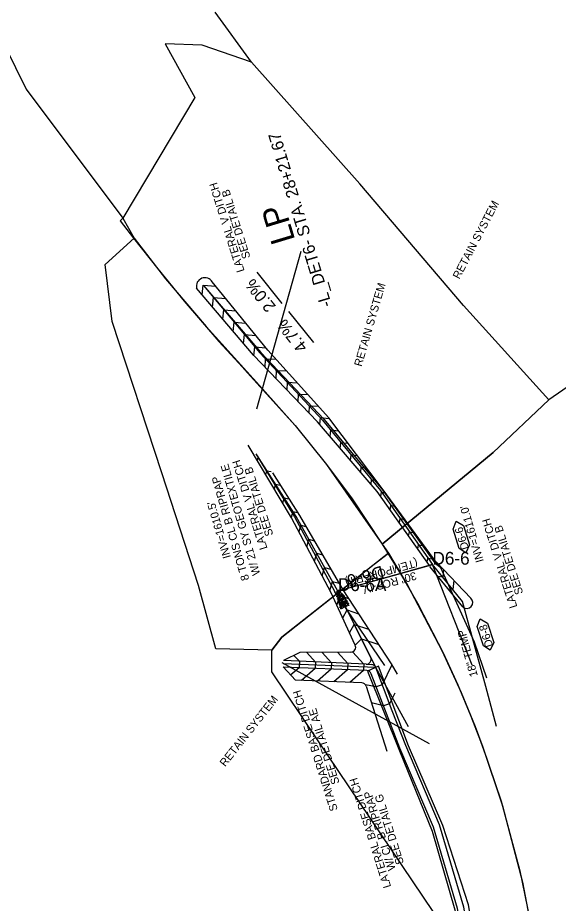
# Model space of a CAD drawing. Extents: x 465700 to 483515, y 488970 to 507540.
# Drawn here: x 474334 to 474671, y 504814 to 505367 of the extents above; entities that cross this region are included whole.
import ezdxf

# ---------------------------------------------------------------- set-up
doc = ezdxf.new("R2010")
doc.units = 0
for name, color, linetype in [('Exist Plan Preparation Watershed Blue', 7, 'Continuous'), ('Prop Drainage Structure Box Number Symbol CELL', 7, 'Continuous'), ('Prop Drainage Structure Pipe Collar Label', 7, 'Continuous'), ('Prop Drainage Structure Pipe RCP 30in Class IV', 7, 'Continuous'), ('Prop Drainage Structure Pipe RCP 30in Class IV Label', 7, 'Continuous'), ('Prop Drainage Structure Pipe Side Drain 18in', 7, 'Continuous'), ('Prop Drainage Structure Pipe Side Drain 18in Label', 7, 'Continuous'), ('Prop Drainage Structure Pipe Stub Out CELL', 7, 'Continuous'), ('Prop Drainage Structure Tops and Inverts LABEL', 7, 'Continuous'), ('Prop Earthen Structure Ditch Flow Line', 7, 'Continuous'), ('Prop Earthen Structure Head Ditch', 7, 'Continuous'), ('Prop Erosion Rip Rap Class B', 7, 'Continuous'), ('Prop Erosion Rip Rap Pad at Outlet CELL', 7, 'Continuous'), ('Prop Erosion Rip Rap Pad at Outlet Label', 7, 'Continuous'), ('Prop Plan Preparation Sag', 7, 'Continuous'), ('Prop Plan Preparation Sag Label', 7, 'Continuous'), ('Scratch_Level_4', 7, 'Continuous'), ('Scratch_Level_8', 7, 'Continuous')]:
    doc.layers.add(name, color=color, linetype=linetype)

msp = doc.modelspace()

# ---------------------------------------------------------------- linework, layer by layer
at = {"layer": 'Exist Plan Preparation Watershed Blue'}
for points in [[(474286.06, 505429.98), (474339.1, 505322.33), (474399.33, 505241.75), (474406.41, 505229.29), (474426.11, 505203.87), (474451.48, 505174.21), (474486.5, 505135.22), (474506.91, 505112.32), (474526.54, 505087.97), (474561.34, 505038.16), (474577.08, 505012.49), (474598.56, 504971.69), (474608.48, 504950.2), (474619.28, 504924.18), (474624.17, 504911.28), (474636.37, 504874.75), (474648.84, 504827.06), (474655.42, 504793.19)], [(474927.77, 504713.75), (474882, 504859.82), (474796.36, 504994.66), (474755.09, 505146.54), (474710.28, 505159.29), (474665.31, 505128.41), (474612.14, 505187.24), (474547.27, 505263.26), (474479.75, 505339.2), (474457.09, 505370.44)]]:
    msp.add_lwpolyline(points, dxfattribs=at)
at = {"layer": 'Prop Drainage Structure Box Number Symbol CELL'}
for points in [[(474609.38, 505035.52), (474605.61, 505047.55), (474607.47, 505052.43), (474612.06, 505049.74), (474615.83, 505037.71), (474613.61, 505032.82), (474609.38, 505035.52)], [(474624.47, 504974.65), (474620.71, 504986.68), (474622.57, 504991.56), (474627.16, 504988.87), (474630.93, 504976.84), (474628.71, 504971.95), (474624.47, 504974.65)]]:
    msp.add_lwpolyline(points, dxfattribs=at)
at = {"layer": 'Prop Drainage Structure Pipe RCP 30in Class IV'}
msp.add_line((474592.73, 505025.37), (474533.61, 505008.87), dxfattribs=at)
at = {"layer": 'Prop Drainage Structure Pipe Side Drain 18in'}
msp.add_line((474625.96, 504949.34), (474611.38, 505002.44), dxfattribs=at)
at = {"layer": 'Prop Drainage Structure Pipe Stub Out CELL'}
msp.add_line((474592.72, 505025.35), (474592.72, 505025.35), dxfattribs=at)
msp.add_line((474592.72, 505025.35), (474592.72, 505025.35), dxfattribs=at)
msp.add_lwpolyline([(474592.72, 505025.36), (474592.74, 505025.35), (474592.73, 505025.33), (474592.71, 505025.34), (474592.72, 505025.36)], dxfattribs=at)
at = {"layer": 'Prop Earthen Structure Ditch Flow Line'}
for p, q in [((474632.62, 504924.28), (474625.96, 504949.34)), ((474576, 504912.31), (474567.64, 504934.12)), ((474572.32, 504910.74), (474566.52, 504925.87))]:
    msp.add_line(p, q, dxfattribs=at)
for points in [[(474622.86, 504705.91), (474617.92, 504758.57), (474608.42, 504810.58), (474593.3, 504861.45), (474572.32, 504910.74)], [(474626.84, 504706.28), (474621.89, 504759.11), (474612.32, 504811.51), (474597.07, 504862.8), (474576, 504912.31)]]:
    msp.add_lwpolyline(points, dxfattribs=at)
at = {"layer": 'Prop Earthen Structure Head Ditch'}
for p, q in [((474611.38, 505002.44), (474592.73, 505025.37)), ((474617.47, 504962.68), (474592.73, 505025.37)), ((474563.04, 504962.47), (474531.69, 505008.33)), ((474590.77, 504913.46), (474498.94, 504963.98)), ((474551.83, 504959.16), (474499.43, 504961.43)), ((474557.29, 504961.03), (474499.52, 504963.42)), ((474551.27, 504963.18), (474499.61, 504965.42)), ((474551.27, 504963.18), (474499.61, 504965.42)), ((474551.27, 504963.18), (474554.62, 504963.04)), ((474567.64, 504934.12), (474557.29, 504961.12)), ((474577.8, 504924.06), (474557.29, 504961.03)), ((474566.96, 504963.46), (474570.74, 504956.86)), ((474566.52, 504925.87), (474554.5, 504957.23)), ((474551.35, 504949.45), (474564.21, 504908.92))]:
    msp.add_line(p, q, dxfattribs=at)
for points in [[(474448.94, 505193.9), (474449.48, 505199.97), (474457.44, 505199.27)], [(474449.69, 505199.72), (474485.49, 505157.78), (474525.05, 505116.04), (474561.61, 505072.06), (474594.66, 505025.9)], [(474449.69, 505199.72), (474485.02, 505157.61), (474524.1, 505115.72), (474560.18, 505071.62), (474592.73, 505025.37)], [(474449.69, 505199.72), (474485.02, 505157.61), (474524.1, 505115.72), (474560.18, 505071.62), (474592.73, 505025.37)], [(474595.59, 505026.16), (474561.96, 505072.17), (474527.96, 505117.02), (474489.96, 505159.41), (474455.27, 505201.93)], [(474590.81, 505024.83), (474558.26, 505071.03), (474520.84, 505114.63), (474481.02, 505156.14), (474445.43, 505198.03)], [(474455.41, 505186.28), (474455.94, 505192.27), (474463.71, 505191.59)], [(474461.88, 505178.67), (474462.4, 505184.57), (474469.97, 505183.91)], [(474468.35, 505171.06), (474468.86, 505176.87), (474476.24, 505176.23)], [(474474.82, 505163.44), (474475.32, 505169.17), (474482.51, 505168.55)], [(474481.28, 505155.83), (474481.78, 505161.48), (474488.77, 505160.86)], [(474488.25, 505148.6), (474488.43, 505153.95), (474495.06, 505153.72)], [(474495.11, 505141.45), (474495.29, 505146.6), (474501.64, 505146.38)], [(474501.97, 505134.29), (474502.15, 505139.25), (474508.22, 505139.04)], [(474508.84, 505127.14), (474509, 505131.91), (474514.8, 505131.7)], [(474515.7, 505119.99), (474515.86, 505124.56), (474521.38, 505124.37)], [(474522.37, 505112.85), (474522.81, 505117.3), (474528.16, 505116.76)], [(474528.76, 505105.39), (474529.18, 505109.52), (474534.02, 505109.03)], [(474544.53, 504975.02), (474529.45, 505007.71), (474504.73, 505054.57), (474477.64, 505100.1)], [(474535.16, 505097.94), (474535.54, 505101.74), (474539.88, 505101.3)], [(474482.42, 505094.57), (474506.59, 505055.15), (474531.69, 505008.33)], [(474554.09, 504967.51), (474533.61, 505008.87), (474507.57, 505055.45), (474483, 505093.9)], [(474557.29, 504961.03), (474533.61, 505008.87), (474507.57, 505055.45), (474483, 505093.9)], [(474541.56, 505090.49), (474541.9, 505093.96), (474545.73, 505093.58)], [(474483.41, 505090.4), (474483.87, 505092.53), (474484.26, 505092.45)], [(474488.72, 505081.48), (474489.29, 505084.06), (474492.04, 505083.46)], [(474492.74, 505082.64), (474509.68, 505056.1), (474536.7, 505009.73), (474566.96, 504963.46)], [(474547.95, 505083.04), (474548.27, 505086.18), (474551.59, 505085.85)], [(474554.35, 505075.58), (474554.63, 505078.4), (474557.45, 505078.12)], [(474494.03, 505072.55), (474494.7, 505075.59), (474497.66, 505074.94)], [(474499.34, 505063.63), (474500.11, 505067.12), (474503.06, 505066.47)], [(474560.46, 505067.91), (474560.92, 505070.57), (474563.45, 505070.13)], [(474566.24, 505059.69), (474566.7, 505062.35), (474569.49, 505061.87)], [(474504.65, 505054.7), (474505.52, 505058.66), (474508.46, 505058.01)], [(474509.4, 505045.71), (474510.62, 505050), (474513.75, 505049.11)], [(474572.03, 505051.48), (474572.49, 505054.13), (474575.53, 505053.6)], [(474577.81, 505043.27), (474578.27, 505045.91), (474581.57, 505045.34)], [(474514.21, 505036.59), (474515.52, 505041.23), (474518.9, 505040.27)], [(474519.02, 505027.48), (474520.42, 505032.45), (474524.06, 505031.43)], [(474583.6, 505035.06), (474584.06, 505037.69), (474587.61, 505037.08)], [(474589.38, 505026.85), (474589.84, 505029.47), (474593.65, 505028.81)], [(474616.67, 505004.4), (474595.21, 505026.99)], [(474523.83, 505018.36), (474525.33, 505023.68), (474529.21, 505022.59)], [(474611.74, 504998.92), (474591.06, 505024.27)], [(474626.66, 504954.4), (474619.05, 504976.87), (474597.95, 505023.39), (474594.66, 505025.9)], [(474599.58, 505022.37), (474599.1, 505017.59), (474596.29, 505017.87)], [(474528.63, 505009.25), (474530.23, 505014.91), (474534.36, 505013.74)], [(474606.03, 505015.53), (474605.46, 505009.81), (474602.64, 505010.09)], [(474532.97, 505000.06), (474535, 505006.07), (474540.26, 505004.29)], [(474536.65, 504992.09), (474539.46, 504997.06), (474546.55, 504994.66)], [(474540.95, 504982.78), (474543.92, 504988.05), (474552.85, 504985.04)], [(474544.53, 504975.02), (474548.38, 504979.05), (474559.14, 504975.41)], [(474541.83, 504970.76), (474509.95, 504970.48), (474499.61, 504965.42)], [(474506.26, 504968.68), (474509.65, 504964.99), (474509.47, 504960.97), (474504.29, 504956.46)], [(474514.22, 504970.52), (474519.69, 504964.55), (474519.51, 504960.53), (474510.98, 504953.1)], [(474523.78, 504970.6), (474529.73, 504964.12), (474529.56, 504960.1), (474521.04, 504952.69)], [(474533.35, 504970.69), (474539.77, 504963.68), (474539.6, 504959.66), (474531.1, 504952.27)], [(474542.77, 504970.92), (474549.81, 504963.25), (474549.64, 504959.23), (474541.16, 504951.85)], [(474548.62, 504951.54), (474507.24, 504953.26), (474499.53, 504961.64)], [(474567.39, 504962.71), (474561.41, 504950.36), (474557.6, 504949.03), (474550.87, 504950.38)], [(474569.14, 504945.1), (474565.92, 504938.46), (474562.12, 504937.14), (474554.68, 504938.96)]]:
    msp.add_lwpolyline(points, dxfattribs=at)
for centre, radius, start, end in [((474450.65, 505199.24), 5.35, 30.2073, 192.9709), ((474614.21, 505001.66), 3.69, 227.9713, 47.9713), ((474541.8, 504973.76), 3, 270.5081, 24.769), ((474551.4, 504966.18), 3, 267.5195, 26.338), ((474554.49, 504960.04), 3, 20.9736, 87.5195), ((474551.7, 504956.16), 3, 20.9736, 87.5195), ((474548.49, 504948.55), 3, 17.5981, 87.629)]:
    msp.add_arc(centre, radius, start, end, dxfattribs=at)
at = {"layer": 'Prop Erosion Rip Rap Class B'}
for p, q in [((474559.04, 504962), (474552.1, 504958.94)), ((474577.66, 504912.17), (474559.04, 504962)), ((474552.1, 504958.94), (474572.16, 504909.07))]:
    msp.add_line(p, q, dxfattribs=at)
msp.add_lwpolyline([(474572.16, 504909.07), (474592.55, 504859), (474606.77, 504809.82), (474615.79, 504757.68), (474620.45, 504704.65), (474625.47, 504653.43), (474631.73, 504706.41), (474624.46, 504759.64), (474615.2, 504812.86), (474599.15, 504862.42), (474577.66, 504912.17)], dxfattribs=at)
at = {"layer": 'Prop Erosion Rip Rap Pad at Outlet CELL'}
msp.add_line((474533.63, 505008.86), (474533.63, 505008.86), dxfattribs=at)
msp.add_line((474533.63, 505008.86), (474533.63, 505008.86), dxfattribs=at)
for points in [[(474532.62, 505007.2), (474532.9, 505007.54), (474533.64, 505008.26), (474534.33, 505008.06), (474534.53, 505007.56), (474533.59, 505006.77), (474532.95, 505006.78), (474532.67, 505007.09)], [(474533.76, 505008.59), (474533.6, 505008.43), (474533.26, 505008.01), (474532.95, 505008.18), (474532.87, 505008.35), (474533.29, 505008.87), (474533.63, 505008.86), (474533.76, 505008.59)], [(474533.63, 505005.56), (474533.35, 505005.62), (474533.02, 505006.01), (474533.13, 505006.31), (474533.3, 505006.39), (474533.76, 505005.96), (474533.76, 505005.71), (474533.63, 505005.56)], [(474533.62, 505004.84), (474533.35, 505004.96), (474533.02, 505005.34), (474533.1, 505005.63), (474533.3, 505005.73), (474533.75, 505005.25), (474533.74, 505005.02), (474533.62, 505004.84)], [(474533.32, 505006.54), (474533.52, 505006.65), (474533.92, 505006.86), (474534.16, 505006.64), (474534.24, 505006.47), (474533.71, 505006.2), (474533.35, 505006.26), (474533.32, 505006.54)], [(474534.6, 505009.16), (474534.44, 505008.99), (474534.07, 505008.55), (474533.8, 505008.75), (474533.71, 505008.92), (474534.11, 505009.39), (474534.46, 505009.43), (474534.6, 505009.16)], [(474536.19, 505003.71), (474535.34, 505003.83), (474533.79, 505004.63), (474533.77, 505005.84), (474534.37, 505006.41), (474536.32, 505005.47), (474536.65, 505004.54), (474536.34, 505003.65)], [(474534.12, 505006.95), (474534.51, 505007.28), (474535.41, 505007.74), (474536.03, 505007.28), (474536.04, 505006.83), (474534.9, 505006.34), (474534.35, 505006.54), (474534.12, 505006.95)], [(474535.02, 505007.57), (474534.72, 505007.76), (474534.25, 505008.19), (474534.37, 505008.72), (474534.73, 505008.9), (474535.31, 505008.19), (474535.27, 505007.83), (474535.02, 505007.57)], [(474535.72, 505005.76), (474535.44, 505005.82), (474535.13, 505006.21), (474535.21, 505006.52), (474535.39, 505006.56), (474535.83, 505006.15), (474535.84, 505005.95), (474535.72, 505005.76)], [(474536.31, 505005.77), (474536.01, 505005.88), (474535.74, 505006.27), (474535.79, 505006.56), (474536, 505006.66), (474536.45, 505006.17), (474536.43, 505005.95), (474536.31, 505005.77)], [(474536.77, 505006.14), (474536.48, 505006.2), (474536.17, 505006.59), (474536.26, 505006.89), (474536.44, 505006.94), (474536.87, 505006.52), (474536.89, 505006.32), (474536.77, 505006.14)], [(474536.35, 505005.76), (474536.65, 505006.04), (474537.19, 505006.31), (474537.62, 505005.95), (474537.62, 505005.61), (474536.81, 505005.3), (474536.47, 505005.5), (474536.35, 505005.76)], [(474537.32, 505003.99), (474537.06, 505004.07), (474536.77, 505004.46), (474536.84, 505004.76), (474537.04, 505004.86), (474537.46, 505004.39), (474537.44, 505004.17), (474537.32, 505003.99)], [(474537.87, 505004.59), (474537.59, 505004.66), (474537.28, 505005.05), (474537.36, 505005.34), (474537.55, 505005.39), (474537.98, 505004.99), (474537.99, 505004.78), (474537.87, 505004.59)], [(474538.46, 505004.56), (474538.37, 505004.31), (474538.05, 505004.02), (474537.7, 505004.06), (474537.55, 505004.35), (474538.05, 505004.69), (474538.36, 505004.73), (474538.46, 505004.56)], [(474533.36, 505004.02), (474533.6, 505004.23), (474534.02, 505004.49), (474534.26, 505004.23), (474534.32, 505003.97), (474533.72, 505003.75), (474533.42, 505003.85), (474533.36, 505004.02)], [(474534.39, 505002.16), (474534.12, 505002.22), (474533.79, 505002.61), (474533.9, 505002.91), (474534.07, 505002.99), (474534.54, 505002.56), (474534.53, 505002.31), (474534.39, 505002.16)], [(474533.85, 505003.3), (474534.01, 505003.63), (474534.53, 505004.11), (474534.96, 505003.99), (474535.09, 505003.72), (474534.5, 505003.07), (474534.07, 505003.07), (474533.85, 505003.3)], [(474534.67, 505001.16), (474534.39, 505001.22), (474534.07, 505001.6), (474534.17, 505001.9), (474534.34, 505001.98), (474534.81, 505001.56), (474534.81, 505001.31), (474534.67, 505001.16)], [(474535.25, 505003.03), (474535.11, 505002.84), (474534.76, 505002.44), (474534.44, 505002.64), (474534.37, 505002.79), (474534.81, 505003.26), (474535.02, 505003.25), (474535.25, 505003.03)], [(474534.55, 505002.21), (474534.98, 505002.54), (474535.92, 505002.91), (474536.46, 505002.5), (474536.54, 505001.96), (474535.43, 505001.51), (474534.73, 505001.71), (474534.55, 505002.21)], [(474535.26, 504999.92), (474534.97, 505000.07), (474534.62, 505000.44), (474534.74, 505000.71), (474534.9, 505000.78), (474535.39, 505000.35), (474535.38, 505000.1), (474535.26, 504999.92)], [(474535.6, 505001.27), (474535.44, 505001.11), (474535.05, 505000.8), (474534.75, 505000.89), (474534.68, 505001.02), (474535.01, 505001.45), (474535.33, 505001.48), (474535.52, 505001.35)], [(474534.81, 504998.83), (474535.05, 504999.04), (474535.46, 504999.29), (474535.71, 504999.04), (474535.77, 504998.77), (474535.17, 504998.55), (474534.87, 504998.65), (474534.81, 504998.83)], [(474534.83, 504999.52), (474535.06, 504999.74), (474535.48, 504999.99), (474535.72, 504999.74), (474535.78, 504999.47), (474535.18, 504999.25), (474534.88, 504999.35), (474534.83, 504999.52)], [(474535.69, 505002.96), (474535.42, 505003.01), (474535.12, 505003.42), (474535.18, 505003.7), (474535.38, 505003.8), (474535.83, 505003.36), (474535.83, 505003.11), (474535.69, 505002.96)], [(474535.92, 505000.2), (474535.77, 505000.34), (474535.37, 505000.69), (474535.53, 505001.03), (474535.7, 505001.11), (474536.19, 505000.64), (474536.07, 505000.4), (474535.92, 505000.2)], [(474535.67, 504998.95), (474536.1, 504999.25), (474536.95, 504999.71), (474537.58, 504999.24), (474537.6, 504998.71), (474536.5, 504998.24), (474535.91, 504998.48), (474535.67, 504998.95)], [(474536.41, 505000.8), (474536.1, 505000.89), (474535.79, 505001.28), (474535.89, 505001.58), (474536.07, 505001.64), (474536.5, 505001.22), (474536.53, 505000.98), (474536.41, 505000.8)], [(474537.21, 505000.22), (474536.98, 504999.91), (474536.4, 504999.48), (474536, 504999.62), (474535.87, 504999.89), (474536.5, 505000.45), (474536.88, 505000.53), (474537.21, 505000.22)], [(474536, 505003.47), (474536.22, 505003.71), (474536.63, 505003.8), (474536.96, 505003.58), (474536.94, 505003.37), (474536.4, 505003.1), (474536.08, 505003.3), (474536, 505003.47)], [(474538.55, 505003.43), (474538.26, 505002.99), (474537.48, 505002.09), (474536.59, 505002.44), (474536.37, 505002.87), (474537.45, 505003.89), (474538.21, 505003.95), (474538.66, 505003.5)], [(474537, 505002.13), (474537.34, 505001.85), (474538.07, 505001.08), (474537.85, 505000.44), (474537.39, 505000.2), (474536.61, 505001.15), (474536.47, 505001.76), (474536.91, 505002.05)], [(474538.2, 505001.42), (474537.96, 505001.49), (474537.57, 505001.9), (474537.68, 505002.2), (474537.86, 505002.24), (474538.33, 505001.82), (474538.36, 505001.62), (474538.2, 505001.42)], [(474537.6, 504999.47), (474537.89, 504999.69), (474538.46, 504999.98), (474538.88, 504999.6), (474538.94, 504999.31), (474538.05, 504998.98), (474537.71, 504999.15), (474537.6, 504999.47)], [(474538.39, 504999.87), (474538.1, 504999.95), (474537.77, 505000.33), (474537.87, 505000.63), (474538.04, 505000.71), (474538.52, 505000.27), (474538.52, 505000.02), (474538.39, 504999.87)], [(474538, 505002.34), (474538.22, 505002.58), (474538.63, 505002.67), (474538.96, 505002.45), (474538.94, 505002.23), (474538.4, 505001.96), (474538.08, 505002.17), (474538, 505002.34)], [(474538.79, 505001.33), (474539.24, 505001.1), (474539.96, 505000.36), (474539.76, 504999.67), (474539.24, 504999.55), (474538.42, 505000.47), (474538.39, 505000.96), (474538.75, 505001.39)], [(474539.15, 505002.54), (474538.86, 505002.6), (474538.55, 505002.99), (474538.62, 505003.29), (474538.81, 505003.33), (474539.24, 505002.93), (474539.26, 505002.73), (474539.15, 505002.54)], [(474539.69, 505002.12), (474539.55, 505001.81), (474539.2, 505001.54), (474538.87, 505001.58), (474538.73, 505001.84), (474539.24, 505002.18), (474539.53, 505002.25), (474539.69, 505002.12)], [(474539.3, 505001.12), (474539.52, 505001.35), (474539.94, 505001.44), (474540.25, 505001.21), (474540.23, 505001), (474539.7, 505000.72), (474539.38, 505000.95), (474539.3, 505001.12)], [(474540.49, 504999.76), (474540.2, 504999.82), (474539.89, 505000.21), (474539.98, 505000.51), (474540.17, 505000.56), (474540.59, 505000.16), (474540.61, 504999.95), (474540.49, 504999.76)], [(474535.39, 504998), (474535.62, 504998.21), (474536.04, 504998.46), (474536.29, 504998.21), (474536.35, 504997.94), (474535.75, 504997.72), (474535.45, 504997.82), (474535.39, 504998)]]:
    msp.add_lwpolyline(points, dxfattribs=at)
at = {"layer": 'Prop Plan Preparation Sag'}
msp.add_line((474483.14, 505122.61), (474510.69, 505221.09), dxfattribs=at)
at = {"layer": 'Prop Plan Preparation Sag Label'}
for p, q in [((474498.83, 505188.5), (474483.21, 505208.02)), ((474502.78, 505183.56), (474518.4, 505164.05))]:
    msp.add_line(p, q, dxfattribs=at)
at = {"layer": 'Scratch_Level_4'}
for points in [[(474425.87, 505350.71), (474444.35, 505317.14), (474399.33, 505241.75), (474397.78, 505240.2), (474406.09, 505229.32), (474421.19, 505210.16), (474437.68, 505189.99), (474459.36, 505164.8), (474486.5, 505135.22), (474506.91, 505112.32), (474526.54, 505087.97), (474542.57, 505066.45), (474561.34, 505038.16), (474630.64, 505095.35), (474665.31, 505128.41), (474612.14, 505187.24), (474547.27, 505263.26), (474479.75, 505339.2), (474448.91, 505349.77)], [(474492.4, 504971.95), (474457.39, 504972.87), (474446.73, 505012.38), (474423.69, 505082.63), (474392.69, 505177.16), (474388.45, 505212.88), (474406.41, 505229.29), (474426.11, 505203.87), (474451.48, 505174.21), (474477.22, 505145.17), (474506.91, 505112.32), (474526.54, 505087.97), (474561.34, 505038.16), (474565.17, 505032.64), (474498.69, 504979.98)], [(474927.77, 504713.75), (474882, 504859.82), (474796.36, 504994.66), (474755.09, 505146.54), (474710.28, 505159.29), (474665.31, 505128.41), (474630.64, 505095.35), (474561.34, 505038.16), (474572.33, 505020.45), (474583.42, 505001.22), (474598.56, 504971.69), (474610.53, 504945.48), (474619.28, 504924.18), (474626.52, 504904.71), (474636.37, 504874.75), (474648.84, 504827.06), (474655.42, 504793.19), (474660.02, 504761.97), (474662.65, 504732.92), (474664.1, 504701.99), (474664.34, 504667.15), (474700.48, 504660.25), (474743.93, 504720.52), (474855.94, 504731.27)], [(474663.84, 504651.25), (474633.28, 504653.85), (474623.58, 504706), (474607.64, 504757.06), (474593.52, 504808.01), (474520.92, 504916.02), (474492.44, 504958.4), (474492.4, 504971.95), (474498.69, 504979.98), (474556.41, 505025.69), (474565.17, 505032.64), (474577.08, 505012.49), (474589.92, 504988.88), (474599.32, 504970.23), (474608.48, 504950.2), (474616.75, 504930.77), (474624.17, 504911.28), (474635.54, 504877.68), (474647.27, 504834.08), (474655.13, 504795.67), (474660.26, 504760.3), (474662.56, 504735.22), (474664.17, 504705.93), (474664.49, 504676.57)]]:
    msp.add_lwpolyline(points, close=True, dxfattribs=at)
at = {"layer": 'Scratch_Level_8'}
msp.add_line((474592.72, 505025.35), (474533.63, 505008.86), dxfattribs=at)

# ---------------------------------------------------------------- texts
at = {"layer": 'Prop Drainage Structure Box Number Symbol CELL'}
for s, p in [('D6-6', (474615.55, 505035.53)), ('D6-8', (474630.65, 504974.64))]:
    msp.add_text(s, height=5, rotation=107.3919, dxfattribs=at).set_placement(p)
at = {"layer": 'Prop Drainage Structure Pipe Collar Label'}
for rotation, p in [(62.3521, (474609.48, 505203.33)), (73.7628, (474548.45, 505148.77)), (51.8094, (474463.32, 504898.79))]:
    msp.add_text('RETAIN SYSTEM', height=5, rotation=rotation, dxfattribs=at).set_placement(p)
at = {"layer": 'Prop Drainage Structure Pipe RCP 30in Class IV Label'}
for s, p in [('(TEMPORARY)', (474582.77, 505029.04)), ('30" RCP-IV', (474581.9, 505021.01))]:
    msp.add_text(s, height=5, rotation=195.5895, dxfattribs=at).set_placement(p)
at = {"layer": 'Prop Drainage Structure Pipe Side Drain 18in Label'}
msp.add_text('18" TEMP', height=5, rotation=105.3524, dxfattribs=at).set_placement((474621.04, 504956.06))
at = {"layer": 'Prop Drainage Structure Pipe Stub Out CELL'}
msp.add_text('SO', height=0.0104, rotation=285.5891, dxfattribs=at).set_placement((474592.71, 505025.35))
at = {"layer": 'Prop Drainage Structure Tops and Inverts LABEL'}
for s, p in [("INV=1610.5'", (474466.87, 505030.04)), ("INV=1611.0'", (474624.76, 505027.56))]:
    msp.add_text(s, height=5, rotation=106.1785, dxfattribs=at).set_placement(p)
at = {"layer": 'Prop Erosion Rip Rap Pad at Outlet Label'}
for s, rotation, p in [('LATERAL V DITCH', 107.389, (474475.48, 505208.85)), ('SEE DETAIL B', 107.389, (474479.12, 505217.32)), ('W/ 21 SY GEOTEXTILE', 106.1785, (474485.23, 505019.49)), ('LATERAL V DITCH', 107.389, (474489.77, 505035.57)), ('SEE DETAIL B', 107.389, (474493.4, 505044.04)), ('8 TONS CL B RIPRAP', 106.1785, (474478.39, 505016.17)), ('LATERAL V DITCH', 107.389, (474645.76, 504999.07)), ('SEE DETAIL B', 107.389, (474649.39, 505007.53)), ('STANDARD BASE DITCH', 107.389, (474533.7, 504872.3)), ('SEE DETAIL AE', 107.389, (474534.76, 504889.01)), ('LATERAL BASE DITCH', 107.389, (474566.97, 504824.26)), ('W/ CL B RIPRAP', 107.389, (474569.85, 504835.15)), ('SEE DETAIL G', 107.389, (474574.94, 504838.96))]:
    msp.add_text(s, height=5, rotation=rotation, dxfattribs=at).set_placement(p)
at = {"layer": 'Prop Plan Preparation Sag Label'}
for s, height, rotation, p in [('-L_DET6- STA. 28+21.67', 7.5, 106.7773, (474529.97, 505187.47)), ('LP', 15, 106.7806, (474507.12, 505228.23)), ('2.0%', 7.5, 128.6712, (474495.28, 505186.81)), ('4.7%', 7.5, 128.6712, (474515.14, 505161.55))]:
    msp.add_text(s, height=height, rotation=rotation, dxfattribs=at).set_placement(p)
at = {"layer": 'Scratch_Level_8'}
for s, p in [('D6-6', (474592.72, 505025.35)), ('D6-6A', (474533.63, 505008.86))]:
    msp.add_text(s, height=8, dxfattribs=at).set_placement(p)
msp.add_text('D6-6', height=8, rotation=195.5858, dxfattribs=at).set_placement((474561.02, 505024.81))

doc.saveas('drawing.dxf')
